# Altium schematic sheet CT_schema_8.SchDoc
size 254 x 194 mm
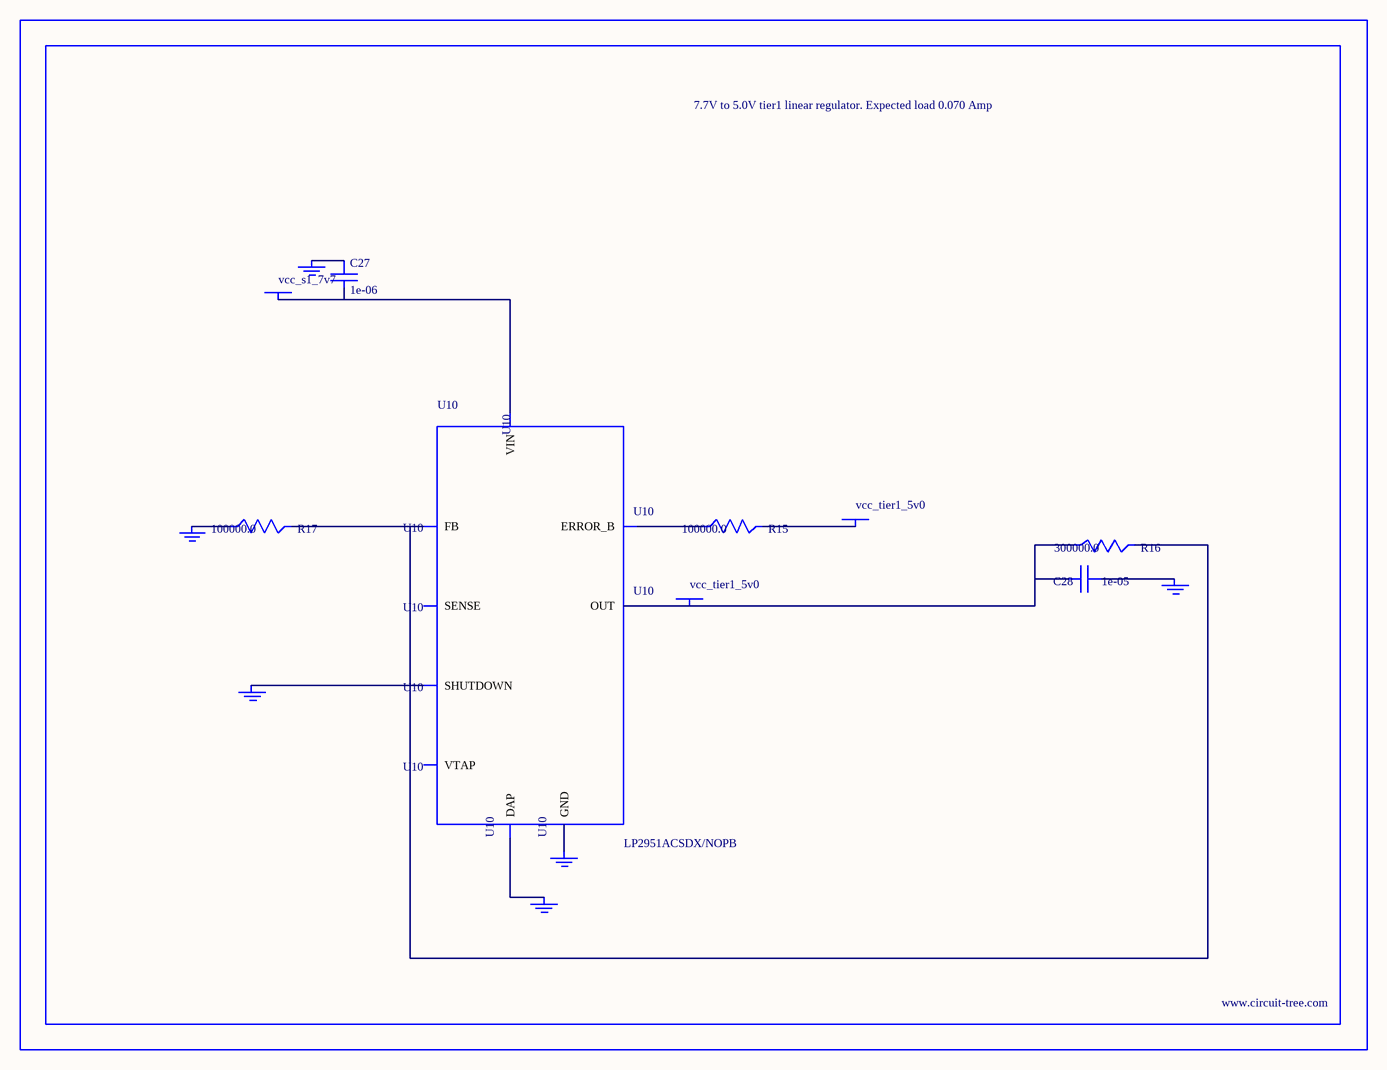
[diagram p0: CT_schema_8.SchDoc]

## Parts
BORDER7  (no value)
C27  1e-06  [C0603]
C28  1e-05  [C1210]
GND_INSTANCE_7_0  (no value)
GND_INSTANCE_7_1  (no value)
GND_INSTANCE_7_2  (no value)
GND_INSTANCE_7_3  (no value)
GND_INSTANCE_7_4  (no value)
GND_INSTANCE_7_5  (no value)
POWER_INSTANCE_7_0  vcc_tier1_5v0
POWER_INSTANCE_7_1  vcc_s1_7v7
POWER_INSTANCE_7_2  vcc_tier1_5v0
R15  100000.0  [R0603]
R16  300000.0  [R0603]
R17  100000.0  [R0603]
U10  LP2951ACSDX/NOPB  [WSON-8]

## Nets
NetC27_1: C27.1 GND_INSTANCE_7_3.0(GND)
NetC27_2: C27.2 POWER_INSTANCE_7_1.0(PWR) U10.8(VIN)
NetC28_1: C28.1 GND_INSTANCE_7_0.0(GND)
NetC28_2: C28.2 POWER_INSTANCE_7_2.0(PWR) R16.1 U10.1(OUT)
NetGND_INSTANCE_7_1_0: GND_INSTANCE_7_1.0(GND) U10.3(SHUTDOWN)
NetGND_INSTANCE_7_2_0: GND_INSTANCE_7_2.0(GND) R17.1
NetGND_INSTANCE_7_4_0: GND_INSTANCE_7_4.0(GND) U10.PAD(DAP)
NetGND_INSTANCE_7_5_0: GND_INSTANCE_7_5.0(GND) U10.4(GND)
NetPOWER_INSTANCE_7_0_0: POWER_INSTANCE_7_0.0(PWR) R15.2
NetR15_1: R15.1 U10.5(ERROR_B)
NetR16_2: R16.2 R17.2 U10.7(FB)

Not connected (* = marked no-connect by the designer): U10 2(SENSE) 6(VTAP)

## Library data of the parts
BORDER7 = BORDER_PAGE7
C27 = C0603C105K3RACTU
C28 = GRM32DR61E106MA12L
GND_INSTANCE_7_0-GND_INSTANCE_7_5 = GND
POWER_INSTANCE_7_0-POWER_INSTANCE_7_2 = PWR
R15 R17 = RC0603JR-07100KL
R16 = RC0603JR-07300KL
